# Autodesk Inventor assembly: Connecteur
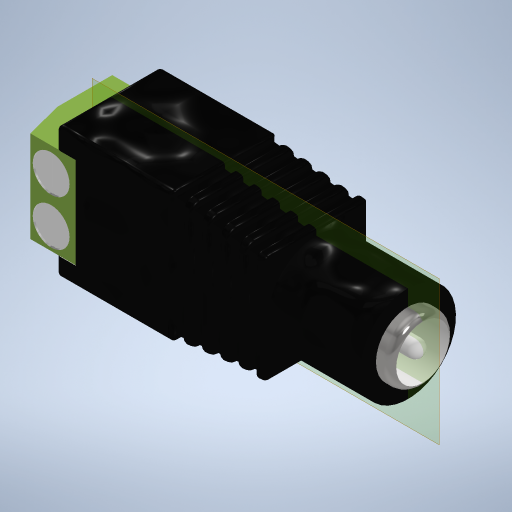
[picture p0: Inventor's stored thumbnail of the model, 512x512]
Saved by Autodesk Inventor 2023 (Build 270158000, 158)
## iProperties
Created: 2025-02
Part Number: Connecteur
Document SubType Name: Assembly
Designer: Buhl
Author: Buhl
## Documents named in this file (3)
- D:\1-Cours-2024-25\1STI2D\IT\Escape-game\Inventor_uhl\Boite\Connecteur\Connecteur.iam
- D:\1-Cours-2024-25\1STI2D\IT\Escape-game\Inventor_uhl\Boite\Connecteur\connecteur.ipt
- D:\1-Cours-2024-25\1STI2D\IT\Escape-game\Inventor_uhl\Boite\Connecteur\Borne.ipt
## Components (2 placed, 2 different names)
1. connecteur:1 — Placage:1, Placage:2, Placage:3
2. Borne:1 — Placage:1, Placage:2, Placage:3
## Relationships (3: Mate 3)
- Placage:1 [Mate]: connecteur:1 ↔ Borne:1
- Placage:2 [Mate]: connecteur:1 ↔ Borne:1
- Placage:3 [Mate]: connecteur:1 ↔ Borne:1
